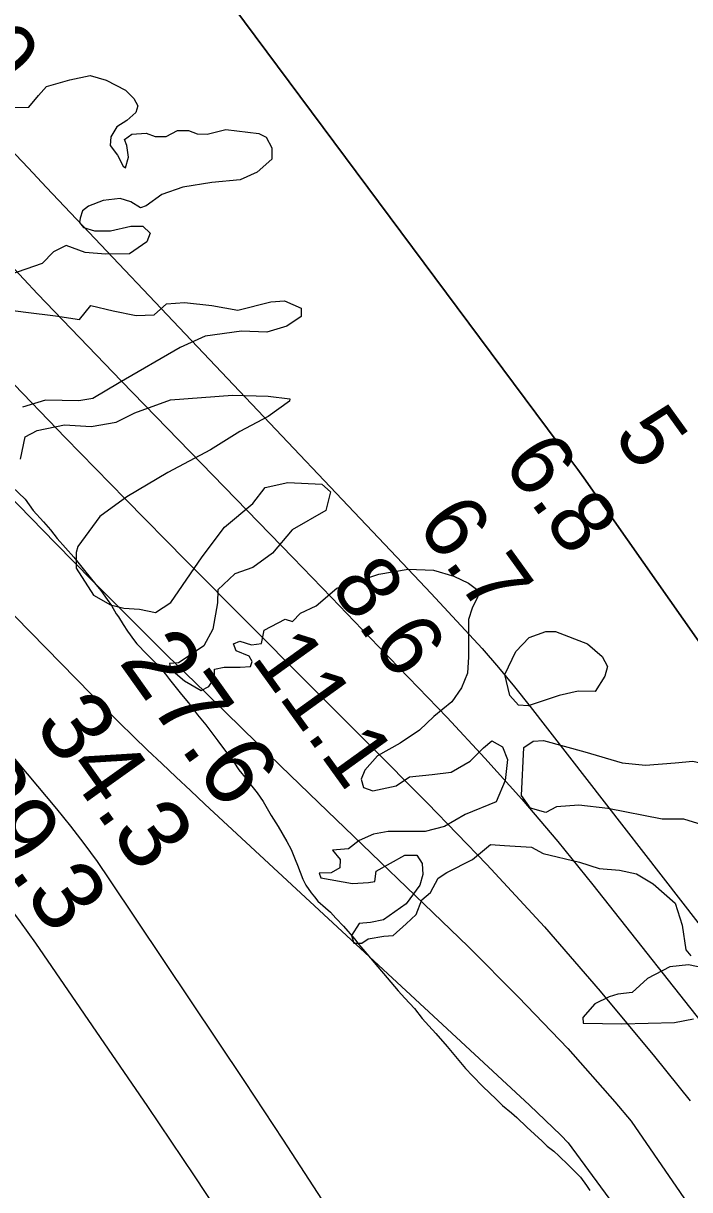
# Model space of a CAD drawing. Extents: x 3245246 to 3283090, y 806824 to 832173.
# Drawn here: x 3269611 to 3270239, y 815112 to 816212 of the extents above; entities that cross this region are included whole.
import ezdxf

# ---------------------------------------------------------------- set-up
doc = ezdxf.new("R2010")
doc.units = 0
for name, color, linetype in [('V-RIVR-EDGE', 7, 'Continuous'), ('V-RIVR-RANG', 7, 'Continuous'), ('V-ROAD-CNTR', 7, 'Continuous'), ('V-SITE-VEGE', 7, 'Continuous'), ('V-TOPO-DPTH', 7, 'Continuous'), ('V-TOPO-MAJR', 7, 'Continuous'), ('V-TOPO-MINR', 7, 'Continuous'), ('V-TOPO-WATR', 7, 'Continuous')]:
    doc.layers.add(name, color=color, linetype=linetype)

msp = doc.modelspace()

# ---------------------------------------------------------------- linework, layer by layer
at = {"layer": 'V-RIVR-EDGE'}
for points in [[(3269600.5, 816132.6), (3269615.7, 816133), (3269624.9, 816143.8), (3269632.3, 816152.5), (3269654.5, 816158.6), (3269673.6, 816162.9), (3269688.8, 816158.5), (3269707, 816148.9), (3269714.8, 816141), (3269718.7, 816134.1), (3269716.6, 816128), (3269708.3, 816120.2), (3269698.7, 816114.5)], [(3269698.7, 816114.5), (3269693, 816105), (3269692.6, 816096.7), (3269699.5, 816087.6), (3269704.7, 816077.1), (3269706.9, 816075.8), (3269709.9, 816085.8), (3269708.2, 816096.7), (3269706.1, 816102.4), (3269713, 816107.5), (3269726.5, 816108.4), (3269734.8, 816105.3), (3269745.2, 816105.3), (3269756.1, 816110.9), (3269766.5, 816110.9), (3269774.7, 816107.8), (3269783.9, 816107.4), (3269801.7, 816111.7), (3269832.6, 816108.1), (3269839.5, 816104.6), (3269845.1, 816094.6), (3269845.1, 816083.8), (3269831.2, 816071.6), (3269815.1, 816064.3), (3269788.5, 816061.7), (3269761.1, 816057.4), (3269741.1, 816050.5), (3269726.3, 816039.7), (3269721.1, 816038), (3269712, 816043.7), (3269702, 816046.7), (3269685.9, 816045), (3269672, 816039.4), (3269666.3, 816035.1), (3269664.1, 816028.1), (3269663.7, 816024.2), (3269667.2, 816019.4), (3269677.6, 816016.4), (3269692.8, 816016.3), (3269711.9, 816020.6), (3269723.2, 816020.6), (3269730.2, 816014.1), (3269727.1, 816005.8), (3269710.6, 815994.5), (3269688, 815994.2), (3269668.8, 815995.9), (3269651, 816002.5), (3269638.9, 815996.5), (3269628.4, 815985.6), (3269597.5, 815974.8)], [(3269578.7, 815944), (3269613.1, 815939.6), (3269640.9, 815936), (3269663.5, 815932.5), (3269674.4, 815945.9), (3269695.2, 815940.7), (3269716.9, 815936.3), (3269733.9, 815937.1), (3269745.7, 815947.5), (3269762.6, 815948.8), (3269788.3, 815945.7), (3269813, 815941.3), (3269843.9, 815949.4), (3269856.9, 815950.3), (3269872.6, 815943.3), (3269872.6, 815935.5), (3269859.1, 815926.4), (3269840.4, 815920.8), (3269816.5, 815921.7), (3269782.1, 815917), (3269758.6, 815906.2), (3269701.1, 815872.9), (3269676.3, 815858.1), (3269662.8, 815856), (3269631.6, 815856.5), (3269609.8, 815850)], [(3269612.3, 815821.8), (3269623.7, 815827.8), (3269649.3, 815833.4), (3269674.5, 815831.6), (3269698, 815835.9), (3269715.9, 815844.6), (3269749.4, 815856.7), (3269808, 815861.3), (3269841.5, 815860.3), (3269861.9, 815857.7), (3269861.5, 815855.5), (3269841.5, 815841.2), (3269814.9, 815826.9), (3269787.1, 815809.6), (3269747, 815788.4), (3269708.3, 815765.5), (3269682.6, 815746.8), (3269662.1, 815718.6), (3269660.3, 815713), (3269660.3, 815698.2), (3269676.7, 815672.5), (3269692.8, 815663.4), (3269705.4, 815660.3), (3269720.2, 815659.4), (3269735.4, 815656.3), (3269749.7, 815665.8), (3269779.4, 815708.8), (3269800.3, 815736.6), (3269826.9, 815759.1), (3269838.7, 815774.3), (3269860, 815779), (3269892.2, 815777.2), (3269900.4, 815770.2), (3269896, 815752.4), (3269864.2, 815734.2), (3269845.5, 815712.1), (3269827.2, 815698.7), (3269810.2, 815692.6), (3269794.1, 815677.5), (3269793.7, 815665.3), (3269789.2, 815640.5), (3269780.9, 815624.9), (3269767, 815615.4), (3269757, 815608.9), (3269748.3, 815608), (3269749.6, 815602.8), (3269762.6, 815591.9), (3269778.2, 815582.7), (3269785.6, 815586.6), (3269790.9, 815594.4), (3269790.9, 815602.7), (3269800, 815604.8), (3269815.2, 815604.8), (3269824.8, 815605.2), (3269826.5, 815610), (3269823.5, 815615.2), (3269811.4, 815620), (3269808.8, 815626.6), (3269814.9, 815629.2), (3269825.7, 815625.6), (3269835.3, 815626.9), (3269837.9, 815639.5), (3269857.5, 815649.9), (3269864.5, 815647.7), (3269871.9, 815655.5), (3269886.7, 815662.4), (3269906.3, 815679.3), (3269945.9, 815692.3), (3269973.7, 815697), (3269997.6, 815696.1), (3270016.7, 815690.4), (3270030.6, 815683.8), (3270039.3, 815677.3), (3270039.3, 815671.2), (3270034, 815660.3), (3270030.5, 815649.5), (3270030.5, 815632.1), (3270030.4, 815614.3), (3270029.5, 815599.1), (3270023.8, 815585.2), (3270014.7, 815572.1), (3269997.7, 815558.3), (3269984.2, 815545.3), (3269965.9, 815533.1), (3269944.6, 815521), (3269932.8, 815507.6), (3269929.3, 815498.9), (3269931.4, 815491.1), (3269940.1, 815488), (3269962.3, 815492.7), (3269974.9, 815501.4), (3269996.2, 815503.5), (3270014.1, 815505.6), (3270031.9, 815516), (3270044.6, 815528.6), (3270052.4, 815535.1), (3270062.4, 815529.4), (3270067.1, 815517.7), (3270064.9, 815497.7), (3270056.6, 815477.7), (3270027.4, 815465.6)], [(3269607.9, 815800.9), (3269612.3, 815821.8)], [(3270112.6, 815638.4), (3270142.6, 815626.6), (3270156.5, 815614.8), (3270161.7, 815605.3), (3270159, 815596.1), (3270149.9, 815581.8), (3270133.8, 815581.9), (3270116, 815578), (3270086.8, 815568.1), (3270077.7, 815569), (3270069.5, 815578.1), (3270064.7, 815597.7), (3270075.2, 815619.4), (3270087.8, 815632.8)], [(3270087.8, 815632.8), (3270103.5, 815638.4), (3270112.6, 815638.4)], [(3270292.3, 815508.9), (3270299.6, 815495.8), (3270299.6, 815484.5), (3270296.1, 815471.9), (3270285.6, 815459.8), (3270270, 815457.2), (3270246.9, 815457.3), (3270233.5, 815461.2), (3270213, 815461.2), (3270161.8, 815471.4), (3270134.4, 815474.5), (3270113.5, 815472.8), (3270103.5, 815467.6), (3270088.8, 815471.6), (3270080.5, 815483.7), (3270082.8, 815528.9), (3270091.5, 815535), (3270101.1, 815535.4), (3270140.2, 815524.9), (3270175.4, 815514.4), (3270197.5, 815512.1), (3270225.3, 815514.3), (3270241.9, 815515.9), (3270258.4, 815512.4)], [(3270027.4, 815465.6), (3270007.9, 815454.4), (3269989.6, 815449.6), (3269954.8, 815449.7), (3269940.9, 815447.1), (3269927.4, 815441.1), (3269917.4, 815433.3), (3269902.2, 815432), (3269909.5, 815423.3), (3269909.1, 815415.5), (3269900.8, 815410.7), (3269889.5, 815410.3), (3269891.2, 815406), (3269921.2, 815400.7), (3269936, 815401.5), (3269942.1, 815402.4), (3269943.4, 815412.4), (3269970.4, 815427.5), (3269981.7, 815427.5), (3269986.9, 815419.6), (3269987.3, 815409.2), (3269984.7, 815399.2), (3269971.6, 815381.4), (3269950.3, 815366.3), (3269938.1, 815363.7), (3269927.2, 815362.8), (3269920.2, 815351.6), (3269922.4, 815344.2), (3269929.8, 815344.2), (3269935.9, 815348.5), (3269950.7, 815351.1), (3269959.4, 815351.5), (3269971.6, 815362.7), (3269981.1, 815371.4), (3269986.4, 815385.3), (3269994.7, 815392.2), (3270001.7, 815405.7), (3270009.9, 815410.9), (3270034.3, 815423.4), (3270051.3, 815437.3), (3270064.3, 815436.4), (3270090, 815435), (3270100.8, 815428.9), (3270135.1, 815420.6), (3270153.8, 815414.9), (3270172.9, 815413.1), (3270189, 815409.6), (3270204.6, 815400.4), (3270225.5, 815382.1), (3270231.9, 815361.2), (3270235.3, 815338.2), (3270240.1, 815332.5)], [(3270220.5, 815322.1), (3270199.2, 815310.9), (3270184.8, 815297.9), (3270171.3, 815296.2), (3270163.1, 815293.6), (3270149.6, 815287.1), (3270138.3, 815274.1), (3270138.7, 815268.9), (3270175.2, 815268.3), (3270224.7, 815269.5), (3270242.6, 815273)], [(3270264.9, 815318.1), (3270237.9, 815323.8), (3270220.5, 815322.1)]]:
    msp.add_lwpolyline(points, dxfattribs=at)
at = {"layer": 'V-ROAD-CNTR'}
msp.add_spline([(3265843.1, 823432.9), (3265859, 823417.1), (3265884.4, 823393.5), (3265921.6, 823385.9), (3265988.6, 823351.1), (3266047.2, 823332.3), (3266110.9, 823317.7), (3266174.6, 823302.5), (3266237.9, 823256.1), (3266319, 823213.7), (3266446.2, 823144), (3266598.2, 823070.2), (3266698.3, 823024.2), (3266809.8, 822977.5), (3266902.8, 822954.7), (3266981.5, 822929.4), (3267047, 822922.9), (3267126.7, 822927), (3267196.8, 822934.5), (3267240.8, 822931.2), (3267315.5, 822929), (3267389.5, 822902.9), (3267472.5, 822855.3), (3267548.2, 822799.1), (3267673.2, 822703.2), (3267729.5, 822659.2), (3267800.8, 822580), (3267841.6, 822514.8), (3267890.4, 822443.6), (3267961.5, 822390.3), (3268026.2, 822347.9), (3268097.5, 822313.7), (3268226.8, 822221.5), (3268328.9, 822136.2), (3268438, 822030.2), (3268539.6, 821913.7), (3268611.4, 821855), (3268669.7, 821833), (3268741.6, 821835.2), (3268781, 821862.3), (3268824.2, 821916.6), (3268873.1, 822006.3), (3268932.5, 822098.1), (3268972.1, 822145.5), (3269019.4, 822162), (3269056, 822158.3), (3269086.7, 822138.7), (3269215.7, 821995.6), (3269467.1, 821682.5), (3269665, 821425.3), (3269890.2, 821132.3), (3269935.6, 821060.8), (3269937.8, 820947), (3269911.9, 820878.4), (3269882.4, 820803.4), (3269850.4, 820754.7), (3269820.8, 820702.9), (3269847.5, 820661.4), (3269995.3, 820504.9), (3270135.1, 820342.3), (3270215.8, 820249.2), (3270280.9, 820161.5), (3270409.8, 819983.2), (3270585.2, 819734.7), (3270723.1, 819531.2), (3270847.8, 819342.2), (3270941.2, 819194.9), (3271024.2, 819065), (3271103.7, 818956), (3271217.9, 818809.2), (3271322.1, 818665), (3271450.9, 818481.1), (3271547.8, 818329.9), (3271656.2, 818159), (3271778.9, 817965.4), (3271939, 817707.5), (3272036.6, 817466.5), (3272126.7, 817285.3), (3272211.9, 817051.1), (3272318, 816867.5), (3272429.4, 816683.2), (3272508.6, 816556.2), (3272571.6, 816398.7), (3272670.4, 816197), (3272779.9, 816022.9), (3272872.1, 815803.2), (3272964.7, 815556.6)], degree=3, dxfattribs=at)
at = {"layer": 'V-SITE-VEGE'}
for p, q in [((3269600.2, 815774.7), (3269612.4, 815763.1)), ((3269612.4, 815763.1), (3269620, 815752.6)), ((3269620, 815752.6), (3269629.6, 815741.8)), ((3269629.6, 815741.8), (3269636.1, 815734.2)), ((3269636.1, 815734.2), (3269642.6, 815726.2)), ((3269642.6, 815726.2), (3269658.3, 815708.5)), ((3269658.3, 815708.5), (3269668.2, 815695.8)), ((3269668.2, 815695.8), (3269679, 815682.7)), ((3269679, 815682.7), (3269683.6, 815676.9)), ((3269683.6, 815676.9), (3269689.7, 815668.6)), ((3269689.7, 815668.6), (3269693.6, 815662.7)), ((3269693.6, 815662.7), (3269698.2, 815655.1)), ((3269698.2, 815655.1), (3269700.5, 815652.2)), ((3269700.5, 815652.2), (3269704.8, 815644.9)), ((3269704.8, 815644.9), (3269709, 815638.7)), ((3269709, 815638.7), (3269715.6, 815629.6)), ((3269715.6, 815629.6), (3269717.5, 815626.7)), ((3269717.5, 815626.7), (3269727, 815617)), ((3269727, 815617), (3269729.7, 815614.4)), ((3269729.7, 815614.4), (3269735.8, 815608.3)), ((3269735.8, 815608.3), (3269737.3, 815605.8)), ((3269737.3, 815605.8), (3269742.7, 815600.3)), ((3269742.7, 815600.3), (3269744.6, 815598.2)), ((3269744.6, 815598.2), (3269748.4, 815593.1)), ((3269748.4, 815593.1), (3269757.3, 815581.9)), ((3269757.3, 815581.9), (3269759.9, 815579)), ((3269759.9, 815579), (3269766.4, 815571)), ((3269766.4, 815571), (3269774.9, 815559.7)), ((3269774.9, 815559.7), (3269782.6, 815550.3)), ((3269782.6, 815550.3), (3269794.1, 815535.1)), ((3269794.1, 815535.1), (3269800.2, 815526.7)), ((3269800.2, 815526.7), (3269809.1, 815515.1)), ((3269809.1, 815515.1), (3269813.7, 815507.8)), ((3269813.7, 815507.8), (3269821, 815499.1)), ((3269821, 815499.1), (3269823.7, 815495.5)), ((3269823.7, 815495.5), (3269831, 815486.1)), ((3269831, 815486.1), (3269836.7, 815478.1)), ((3269836.7, 815478.1), (3269844.5, 815464.9)), ((3269844.5, 815464.9), (3269851.1, 815454.4)), ((3269851.1, 815454.4), (3269859.2, 815440.1)), ((3269859.2, 815440.1), (3269863.1, 815432.8)), ((3269863.1, 815432.8), (3269867.1, 815423.3)), ((3269867.1, 815423.3), (3269869.1, 815417.8)), ((3269869.1, 815417.8), (3269874.3, 815404.6)), ((3269874.3, 815404.6), (3269877, 815399.1)), ((3269877, 815399.1), (3269882, 815391.9)), ((3269882, 815391.9), (3269885.1, 815387.9)), ((3269885.1, 815387.9), (3269888.5, 815383.9)), ((3269888.5, 815383.9), (3269895.7, 815377.8)), ((3269895.7, 815377.8), (3269900.3, 815373.5)), ((3269900.3, 815373.5), (3269905.3, 815368)), ((3269905.3, 815368), (3269912.5, 815360.5)), ((3269912.5, 815360.5), (3269922.8, 815348.5)), ((3269922.8, 815348.5), (3269927, 815343.1)), ((3269927, 815343.1), (3269934.7, 815334.4)), ((3269934.7, 815334.4), (3269964.2, 815299.3)), ((3269964.2, 815299.3), (3269970.3, 815292.4)), ((3269970.3, 815292.4), (3269979.4, 815282.6)), ((3269979.4, 815282.6), (3269986.7, 815273.2)), ((3269986.7, 815273.2), (3269993.2, 815266.3)), ((3269993.2, 815266.3), (3269999.7, 815259.1)), ((3269999.7, 815259.1), (3270010.4, 815246.8)), ((3270010.4, 815246.8), (3270027.6, 815226.2)), ((3270027.6, 815226.2), (3270034.1, 815219.3)), ((3270034.1, 815219.3), (3270044, 815209.2)), ((3270044, 815209.2), (3270056.5, 815197.3)), ((3270056.5, 815197.3), (3270062.6, 815191.2)), ((3270062.6, 815191.2), (3270071, 815184.4)), ((3270071, 815184.4), (3270075.9, 815180)), ((3270075.9, 815180), (3270085.4, 815170.7)), ((3270085.4, 815170.7), (3270099.8, 815157.7)), ((3270099.8, 815157.7), (3270104.8, 815153)), ((3270104.8, 815153), (3270110.8, 815148)), ((3270110.8, 815148), (3270115.8, 815143.7)), ((3270115.8, 815143.7), (3270124.9, 815135.1)), ((3270124.9, 815135.1), (3270130.6, 815128.9)), ((3270130.6, 815128.9), (3270136, 815123.5)), ((3270136, 815123.5), (3270141.7, 815115.9)), ((3270141.7, 815115.9), (3270144.8, 815111.2))]:
    msp.add_line(p, q, dxfattribs=at)
at = {"layer": 'V-TOPO-DPTH'}
for points in [[(3269246.5, 816367.8), (3269391.4, 816208.1), (3269429.9, 816165.9), (3269468.4, 816123.8), (3269507.1, 816081.9), (3269545.9, 816040), (3269584.9, 815998.3), (3269624.1, 815956.8), (3269663.5, 815915.6), (3269703.1, 815874.5), (3269864.7, 815708), (3269901.1, 815670.4), (3269937.5, 815632.7), (3269973.9, 815595), (3270010.2, 815557.3), (3270045.9, 815519), (3270080.9, 815480.1), (3270114.7, 815440.1), (3270147.8, 815399.5), (3270265.1, 815251), (3270292.9, 815213.8)], [(3270525.8, 815293.7), (3270512.2, 815305.7), (3270464.6, 815350.7), (3270419.3, 815397.9), (3270377.5, 815448.1), (3270338, 815500.4), (3270155.4, 815760.6), (3270148.1, 815770.8), (3270140.9, 815781), (3270133.5, 815791.1), (3270126.1, 815801.2), (3269734, 816328.1)], [(3270525.8, 815293.7), (3270512.2, 815305.7), (3270464.6, 815350.7), (3270419.3, 815397.9), (3270377.5, 815448.1), (3270338, 815500.4), (3270155.4, 815760.6), (3270148.1, 815770.8), (3270140.9, 815781), (3270133.5, 815791.1), (3270126.1, 815801.2), (3269734, 816328.1)]]:
    msp.add_lwpolyline(points, dxfattribs=at)
at = {"layer": 'V-TOPO-MAJR'}
for points in [[(3268929.6, 816311.9), (3269130.9, 816128.6), (3269156.5, 816104.8), (3269181.8, 816080.8), (3269206.7, 816056.4), (3269231.4, 816031.7), (3269255.8, 816006.7), (3269280.2, 815981.8), (3269304.6, 815956.8), (3269329.1, 815931.9), (3269674.8, 815578.9), (3269687.9, 815565.6), (3269701, 815552.5), (3269714.4, 815539.4), (3269727.7, 815526.5), (3269741.2, 815513.7), (3269754.7, 815500.9), (3269768.3, 815488.2), (3269781.9, 815475.5), (3270088, 815191.6), (3270117.4, 815163.3), (3270124.5, 815156.1)], [(3270124.5, 815156.1), (3270836, 814188), (3270870.1, 814134.1), (3270906.1, 814081.7), (3270945.3, 814031.6), (3271487.9, 813229.8)]]:
    msp.add_lwpolyline(points, dxfattribs=at)
at = {"layer": 'V-TOPO-MINR'}
for points in [[(3269220.5, 816518.4), (3269495, 816207.5), (3269511.9, 816188.4), (3269528.8, 816169.4), (3269545.9, 816150.5), (3269563, 816131.6), (3269580.3, 816112.9), (3269597.6, 816094.2), (3269615, 816075.6), (3269632.5, 816057), (3269962.7, 815708.7), (3269979, 815691.5), (3269995.2, 815674.3), (3270011.3, 815657), (3270027.4, 815639.7), (3270043.3, 815622.2), (3270058.8, 815604.3), (3270073.9, 815586.1), (3270088.6, 815567.6), (3270284, 815315.9), (3270345.9, 815232)], [(3269246.5, 816367.8), (3269391.4, 816208.1), (3269429.9, 816165.9), (3269468.4, 816123.8), (3269507.1, 816081.9), (3269545.9, 816040), (3269584.9, 815998.3), (3269624.1, 815956.8), (3269663.5, 815915.6), (3269703.1, 815874.5), (3269864.7, 815708), (3269901.1, 815670.4), (3269937.5, 815632.7), (3269973.9, 815595), (3270010.2, 815557.3), (3270045.9, 815519), (3270080.9, 815480.1), (3270114.7, 815440.1), (3270147.8, 815399.5), (3270265.1, 815251), (3270292.9, 815213.8)], [(3268846.7, 816279.9), (3269160.1, 815987.8), (3269169.5, 815978.8), (3269178.9, 815969.9), (3269188.2, 815960.8), (3269197.5, 815951.6), (3269206.7, 815942.4), (3269215.8, 815933.2), (3269224.9, 815923.9), (3269234, 815914.6), (3269384.3, 815760.6), (3269433.7, 815708.9), (3269482.4, 815656.4), (3269529.9, 815602.8), (3269576.6, 815548.6), (3269641.8, 815471.1), (3269655, 815454.8), (3269667.8, 815438.3), (3269680.1, 815421.4), (3269692, 815404.2), (3269819.1, 815213.9), (3269855.7, 815158.5), (3269891.9, 815102.9)], [(3269142.8, 816232.2), (3269184.4, 816193.1), (3269225, 816153), (3269264.9, 816112.3), (3269304.3, 816071), (3269343.8, 816029.8), (3269383.4, 815988.6), (3269423, 815947.5), (3269606.3, 815757.3), (3269641, 815721.6), (3269675.9, 815686.1), (3269711, 815650.9), (3269746.4, 815615.8), (3269782, 815581), (3269817.6, 815546.2), (3269853.3, 815511.6), (3269889.1, 815477), (3270030, 815341.1), (3270077.6, 815293.5), (3270124, 815244.9), (3270168.6, 815194.6), (3270184, 815176.5)], [(3269272.9, 816220.4), (3269298, 816193.4), (3269352.3, 816135.3), (3269406.7, 816077.2), (3269461.2, 816019.3), (3269515.8, 815961.5), (3269538, 815938.1), (3269594, 815879.4), (3269650.3, 815821), (3269707, 815763), (3269764, 815705.2), (3269765.2, 815704), (3269821.8, 815647), (3269878.4, 815590.1), (3269935.1, 815533.2), (3269991.8, 815476.4), (3270047.6, 815418.7), (3270102, 815359.8), (3270154.6, 815299.2), (3270205.8, 815237.5), (3270239.5, 815195.5)], [(3268851.4, 816162.6), (3268873.4, 816139), (3268895.2, 816115.1), (3269076.4, 815913.7), (3269099.7, 815888.6), (3269123.5, 815864), (3269148.1, 815840.1), (3269173.2, 815816.8), (3269231.6, 815764.2), (3269285.4, 815714.1), (3269338.2, 815663), (3269389.4, 815610.2), (3269439.5, 815556.4), (3269560.6, 815422.3), (3269576.9, 815403.5), (3269592.7, 815384.3), (3269607.7, 815364.5), (3269622.2, 815344.3), (3269683.2, 815255.4), (3269727.6, 815190.2), (3269771.7, 815124.8), (3269815.2, 815059.1)], [(3270184, 815176.5), (3270802.6, 814275.7), (3270836.5, 814222.5), (3270871.9, 814170.3), (3270909.4, 814119.7), (3270948.4, 814070.1), (3271517.8, 813231.2)]]:
    msp.add_lwpolyline(points, dxfattribs=at)
at = {"layer": 'V-TOPO-WATR'}
msp.add_lwpolyline([(3269734, 816328.1), (3270126.1, 815801.2), (3270133.5, 815791.1), (3270140.9, 815781), (3270148.1, 815770.8), (3270155.4, 815760.6), (3270338, 815500.4), (3270377.5, 815448.1), (3270419.3, 815397.9), (3270464.6, 815350.7), (3270512.2, 815305.7), (3270525.8, 815293.7)], dxfattribs=at)

# ---------------------------------------------------------------- texts
at = {"layer": 'V-RIVR-RANG'}
for s, height, rotation, p in [('7.0', 60, 307.0349, (3269514.9, 816236.6)), ('5', 60, 305.7778, (3270166.3, 815823)), ('6.8', 60, 305.7778, (3270061.6, 815797.2)), ('6.7', 60, 305.7778, (3269980.6, 815738.6)), ('8.6', 60, 305.7778, (3269898.8, 815681)), ('27.6', 67, 305.5183, (3269699.9, 815609.8)), ('11.1', 60, 305.7778, (3269824.6, 815613)), ('34.3', 67, 305.5183, (3269619.8, 815550)), ('39.3', 67, 305.5183, (3269538.5, 815491.7))]:
    msp.add_text(s, height=height, rotation=rotation, dxfattribs=at).set_placement(p)

doc.saveas('drawing.dxf')
